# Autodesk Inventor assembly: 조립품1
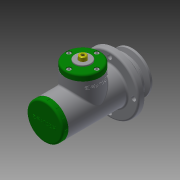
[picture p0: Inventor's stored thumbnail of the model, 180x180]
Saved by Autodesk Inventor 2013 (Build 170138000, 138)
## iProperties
Created: 2016-08
Part Number: 조립품1
Document SubType Name: Assembly
Designer: Administrator
Author: Administrator
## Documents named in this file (25)
- C:\Users\Administrator\Desktop\460808V1014\조립품1.iam
- C:\Users\Administrator\Desktop\460808V1014\본체.ipt
- C:\Users\Administrator\Desktop\460808V1014\V-벨트풀리.ipt
- C:\Users\Administrator\Desktop\460808V1014\편심축.ipt
- C:\Users\Administrator\Desktop\460808V1014\너트 M10.ipt
- C:\Users\Administrator\Desktop\460808V1014\링크.ipt
- C:\Users\Administrator\Desktop\460808V1014\멈춤링 15 x 1.ipt
- C:\Users\Administrator\Desktop\460808V1014\멈춤링 35x1.6.ipt
- C:\Users\Administrator\Desktop\460808V1014\베어링 15 x 35 x 11.ipt
- C:\Users\Administrator\Desktop\460808V1014\볼트 M4 x 10.ipt
- C:\Users\Administrator\Desktop\460808V1014\볼트 M4 x 12.ipt
- C:\Users\Administrator\Desktop\460808V1014\부시1.ipt
- C:\Users\Administrator\Desktop\460808V1014\부시2.ipt
- C:\Users\Administrator\Desktop\460808V1014\분할핀 1.6 x 12.ipt
- C:\Users\Administrator\Desktop\460808V1014\사이드 커버.ipt
- 사이드 커버.ipt
- C:\Users\Administrator\Desktop\460808V1014\슬라이더.ipt
- C:\Users\Administrator\Desktop\460808V1014\오일 실 15 25 7.ipt
- C:\Users\Administrator\Desktop\460808V1014\와셔 4x16.ipt
- C:\Users\Administrator\Desktop\460808V1014\와셔 10x21.ipt
- C:\Users\Administrator\Desktop\460808V1014\클래스터 핀 6 x 24.ipt
- C:\Users\Administrator\Desktop\460808V1014\키 4 x 4 x 18.ipt
- C:\Users\Administrator\Desktop\460808V1014\탑 부시.ipt
- C:\Users\Administrator\Desktop\460808V1014\탑 커버.ipt
- 탑 커버.ipt
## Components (6 placed, 3 different names)
1. V-벨트풀리:2
2. ISO 4017 M4 x 10:1
3. ISO 4762 M4 x 12:1
4. ISO 4762 M4 x 12:2
5. ISO 4762 M4 x 12:3
6. ISO 4762 M4 x 12:4
